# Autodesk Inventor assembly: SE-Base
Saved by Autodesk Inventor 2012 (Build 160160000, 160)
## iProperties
Created: 2013-08
Part Number: SE-Base
Document SubType Name: Assembly
Designer: hilarion
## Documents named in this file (6)
- D:\dominique\travail\année 2013-2014\TSTI2D\ITEC\Révision inventor\webcam motorisé\Composants importés\Webcam motorisee\SE-Base.iam
- D:\dominique\travail\année 2013-2014\TSTI2D\ITEC\Révision inventor\webcam motorisé\Composants importés\Webcam motorisee\Base.ipt
- D:\dominique\travail\année 2013-2014\TSTI2D\ITEC\Révision inventor\webcam motorisé\Composants importés\Webcam motorisee\Moto-reducteur vertical.ipt
- D:\dominique\travail\année 2013-2014\TSTI2D\ITEC\Révision inventor\webcam motorisé\Composants importés\Webcam motorisee\Socle.ipt
- D:\dominique\travail\année 2013-2014\TSTI2D\ITEC\Révision inventor\webcam motorisé\Composants importés\Webcam motorisee\Semelle.ipt
- D:\dominique\travail\année 2013-2014\TSTI2D\ITEC\Révision inventor\webcam motorisé\Composants importés\Webcam motorisee\cache_réducteur.ipt
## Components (5 placed, 5 different names)
1. Base:1
2. Moto-reducteur vertical:1
3. Socle:1
4. Semelle:1
5. cache_réducteur:1
